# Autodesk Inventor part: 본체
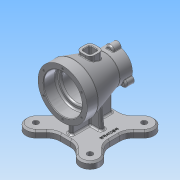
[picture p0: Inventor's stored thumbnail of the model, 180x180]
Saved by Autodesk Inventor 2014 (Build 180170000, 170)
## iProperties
Created: 2018-03
Part Number: 본체
Material: 알루미늄 6061
Document SubType Name: Modeling
Designer: 703
Density: 2.71 g/cm^3
Appearance: 알루미늄 - 평지
Mass: 1015 g
Surface Area: 853.881 cm^2
Volume: 374.54 cm^3
Author: 703
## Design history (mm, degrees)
sketch "스케치1"
  geometry: L1 (45, -45)-(-45, -45); L2 (-45, -45)-(-45, 45); L3 (-45, 45)-(45, 45); L4 (45, 45)-(45, -45); L5 (45, -45)-(-45, 45); L6 (-45, -45)-(45, 45); 1 further point
  constraints: 12 end point, 2 midpoint, 2 parallel, 1 horizontal, 1 perpendicular
  dimensions: "d0" = 90 distance of L2.end L3.end; "d1" = 90 distance of L1.end L2.end
extrude "돌출1" new body sketch "스케치1" distance "d2" = 12; taper "d3" = 0 deg
sketch "스케치2" dims "d4" = 140
  geometry: L1 (45, -45)-(45, 45) reference; L2 (45, 45)-(-45, 45) reference; L3 (0, 0)-(53.436, 53.436); L4 (0, 0)-(75.571, 0); L5 (36.77, 62.225)-(19.544, 45); L6 (62.225, 36.77)-(45, 19.544); A1 r 18 centre (49.497, 49.497) between (62.225, 36.77) and (36.77, 62.225); 1 further point
  constraints: 8 end point, 3 point on line, 2 parallel, 2 point on circle, 2 tangent, 1 centre point, 1 coincident, 1 equal length, 1 horizontal, 3 other
  dimensions: "d5" = 45 deg angle of L4 L3; "d6" = 36 diameter of A1
extrude "돌출2" join sketch "스케치2" distance "d7" = 12; taper "d8" = 0 deg
sketch "스케치3"
  geometry: L1 (-50, 82)-(50, 82); L2 (-50, 82)-(-50, 127); L3 (-50, 127)-(-30, 127); L4 (-30, 127)-(27, 109.5); L5 (27, 109.5)-(50, 109.5); L6 (50, 109.5)-(50, 82); 2 further points
  constraints: 12 end point, 2 perpendicular, 1 horizontal, 1 midpoint, 1 parallel, 1 vertical alignment
  dimensions: "d12" = 82 distance from line of point (0, 0) L1; "d13" = 20 distance of L2.end L3.end; "d14" = 90 diameter of L3 L1; "d15" = 100 distance between parallel lines of L6 L2; "d16" = 77 horizontal distance of L2.end L4.end; "d17" = 55 diameter of L5 L1
revolve "회전1" sketch "스케치3" stored, may be unused: angle "d18" = 90 deg
sketch "스케치5"
  geometry: L1 (-37, 12)-(37, 12); L2 (37, 12)-(37, 70); L3 (37, 70)-(-37, 70); L4 (-37, 70)-(-37, 12); L5 (-37, 12)-(37, 70); L6 (37, 12)-(-37, 70); L7 (19.544, 12)-(-19.544, 12) reference; 3 further points
  constraints: 12 end point, 3 midpoint, 2 parallel, 1 collinear, 1 horizontal, 1 perpendicular, 1 vertical alignment
  dimensions: "d25" = 37 distance from line of point (0, 0) L4; "d26" = 70 distance from line of point (0, 0) L3
extrude "돌출3" join sketch "스케치5" stored distance "d27" = 8; taper "d28" = 0 deg
sketch "스케치6"
  geometry: L1 (-19.801, 60)-(-24, 12); L2 (-24, 12)-(24, 12); L3 (-36.77, 12)-(-67.497, 12) reference; L4 (-19.801, 60)-(19.801, 60); L5 (-36.77, 12)-(-19.544, 12) reference; L6 (24, 12)-(19.801, 60); L7 (67.497, 12)-(36.77, 12) reference; 3 further points
  constraints: 8 end point, 2 collinear, 1 parallel
  dimensions: "d29" = 24 horizontal distance of point (0, 0) L1.end; "d30" = 95 deg angle of L5 L1; "d32" = 24 horizontal distance of point (0, 0) L2.end; "d33" = 60 distance from line of point (0, 0) L4; "d34" = 95 deg angle of L7 L6
extrude "돌출4" join sketch "스케치6" stored distance "d35" = 8; taper "d36" = 0 deg
sketch "스케치4"
  geometry: L1 (-50, 37)-(-50, 127) reference; L2 (-50, 82)-(50, 82); L3 (-50, 82)-(-50, 117); L4 (-50, 117)-(-30, 117); L5 (-27, 114)-(-27, 111); L6 (-24, 108)-(17, 108); L7 (20, 105)-(20, 105); L8 (23, 102)-(50, 102); L9 (50, 54.5)-(50, 109.5) reference; L10 (50, 102)-(50, 82); A1 r 3 centre (-30, 114) between (-27, 114) and (-30, 117); A2 r 3 centre (-24, 111) between (-27, 111) and (-24, 108); A3 r 3 centre (17, 105) between (20, 105) and (17, 108); A4 r 3 centre (23, 105) between (20, 105) and (23, 102); 4 further points
  constraints: 16 end point, 8 point on circle, 8 point on line, 8 tangent, 4 centre point, 3 equal radius, 3 perpendicular, 2 parallel, 1 collinear, 1 midpoint, 1 vertical
  dimensions: "d19" = 40 diameter of L8 L2; "d20" = 52 diameter of L6 L2; "d21" = 23 distance of L3.end point (-27, 117); "d22" = 70 diameter of L4 L2; "d23" = 47 distance of point (-27, 108) point (20, 108); "d24" = 3 radius of A1
revolve "회전2" sketch "스케치4" stored, may be unused: angle "d37" = 90 deg
chamfer "모따기1" distance "d38" = 1; stored, may be unused: second distance "d39" = 2, angle "d40" = 45 deg
node "작업 평면1"
sketch "스케치7"
  geometry: L1 (-12.5, 12.5)-(12.5, 12.5); L2 (12.5, 12.5)-(12.5, -12.5); L3 (12.5, -12.5)-(-12.5, -12.5); L4 (-12.5, -12.5)-(-12.5, 12.5); L5 (-12.5, 12.5)-(12.5, -12.5); L6 (12.5, 12.5)-(-12.5, -12.5); 1 further point
  constraints: 12 end point, 2 midpoint, 2 parallel, 1 horizontal, 1 perpendicular
  dimensions: "d42" = 25 distance of L2.end L3.end; "d43" = 25 distance of L1.end L2.end
extrude "돌출5" join sketch "스케치7" stored distance "d44" = 8; taper "d45" = 0 deg
sketch "스케치8"
  geometry: L1 (-7.5, -7.5)-(7.5, -7.5); L2 (7.5, -7.5)-(7.5, 7.5); L3 (7.5, 7.5)-(-7.5, 7.5); L4 (-7.5, 7.5)-(-7.5, -7.5); L5 (-7.5, -7.5)-(7.5, 7.5); L6 (7.5, -7.5)-(-7.5, 7.5); 1 further point
  constraints: 12 end point, 2 midpoint, 2 parallel, 1 horizontal, 1 perpendicular
  dimensions: "d46" = 15 distance of L3.end L2.end; "d47" = 15 distance of L2.end L1.end
extrude "돌출6" cut sketch "스케치8" stored distance "d48" = 8; taper "d49" = 0 deg
fillet "모깎기1" dims "d50" = 8
fillet "모깎기2" dims "d51" = 3
sketch "스케치9"
  geometry: A1 r 27.5 centre (0, 0) between (0, -27.5) and (6.943, -26.609) reference; A2 r 7 centre (0, -27.5) between (-6.943, -26.609) and (6.943, -26.609); 1 further point
  constraints: 5 point on circle, 1 centre point, 1 vertical alignment
  dimensions: "d53" = 7 radius of A2
extrude "돌출7" join sketch "스케치9" distance "d54" = 15; taper "d55" = 0 deg
fillet "모깎기3" dims "d56" = 3
fillet "모깎기4" dims "d57" = 1
sketch "스케치10"
  geometry: A1 r 7 centre (0, 0) between (-6.999, 0.127) and (6.999, 0.127) reference; 1 further point
hole "구멍1" sketch "스케치10" at (0, 0) diameter "d58" = 3.242; stored, may be unused: countersink angle "d62" = 90 deg, drill point angle "d64" = 118 deg; dims "d59" = 9, "d60" = 4, "d61" = 2, "d63" = 11
fillet "모깎기5" dims "d68" = 3
fillet "모깎기6" dims "d69" = 25
fillet "모깎기7" dims "d70" = 3
fillet "모깎기8" dims "d71" = 3
fillet "모깎기9" dims "d72" = 1
sketch "스케치11"
  geometry: A1 r 15 centre (-49.497, 49.497) between (-38.891, 60.104) and (-60.104, 38.891) reference; A2 r 15 centre (-49.497, -49.497) between (-60.104, -38.891) and (-38.891, -60.104) reference; A3 r 15 centre (49.497, -49.497) between (38.891, -60.104) and (60.104, -38.891) reference; A4 r 15 centre (49.497, 49.497) between (60.104, 38.891) and (38.891, 60.104) reference; 1 further point
hole "구멍2" sketch "스케치11" at (-49.497, -49.497), (49.497, -49.497), (49.497, 49.497), (-49.497, 49.497) diameter "d73" = 10; stored, may be unused: countersink angle "d77" = 90 deg, drill point angle "d79" = 118 deg; dims "d74" = 9, "d75" = 4, "d76" = 2, "d78" = 11
sketch "스케치12"
  geometry: C1 r 45 at (0, 0) reference; C2 r 36 at (0, 0) reference; 7 further points
  constraints: 1 vertical alignment, 7 other
  dimensions: "d80" = 40 distance of C1.centre point (0, 40); "d83" = 360 deg dimension on C2.centre point (0, 40) (derived)
hole "구멍3" sketch "스케치12" at (0, 40), (-34.641, 20), (-34.641, -20), (0, -40), (34.641, -20), (34.641, 20) diameter "d85" = 3.242; stored, may be unused: countersink angle "d89" = 90 deg, drill point angle "d91" = 118 deg; dims "d86" = 9, "d87" = 4, "d88" = 2, "d90" = 11
chamfer "모따기2" distance "d92" = 1; stored, may be unused: second distance "d93" = 2, angle "d94" = 45 deg
chamfer "모따기3" distance "d95" = 3; stored, may be unused: second distance "d96" = 2, angle "d97" = 45 deg
sketch "스케치13"
  geometry: L1 (9.189, 45)-(-9.189, 45) reference; 2 further points
  constraints: 1 other
  dimensions: "d98" = 35 distance of point (35, 0) point (0, 0); "d99" = 45 distance from line of point (35, 0) L1
feature "엠보싱1" sketch "스케치13" dims "d0" = 90, "d1" = 90, "d100" = 0.5, "d101" = 0
node "솔리드1"
pattern_circular "원형 패턴1" dims angle "d10" = 360 deg
pattern_circular "원형 패턴2" dims "d66" = 360 deg
other parameters: "d41" = 127, "d52" = 14
